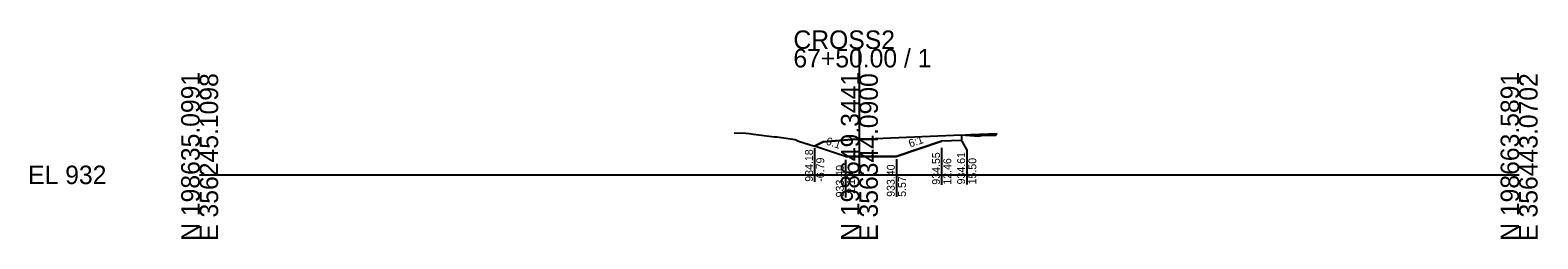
# Model space of a CAD drawing. Extents: x -26 to 203, y -10 to 14021.
# Drawn here: x -25.7 to 202.8, y 8490.3 to 8521.9 of the extents above; entities that cross this region are included whole.
import ezdxf

# ---------------------------------------------------------------- set-up
doc = ezdxf.new("R2010")
doc.units = 0
for name, color, linetype in [('Default', 7, 'Continuous'), ('P_E_XS_Ground', 7, 'Continuous'), ('P_XS', 7, 'Continuous'), ('P_XS_EAR_CommonGrnd', 7, 'Continuous'), ('P_XS_Lane', 7, 'Continuous'), ('P_XS_Rock', 7, 'Continuous')]:
    doc.layers.add(name, color=color, linetype=linetype)

msp = doc.modelspace()

# ---------------------------------------------------------------- linework, layer by layer
at = {"layer": 'Default'}
for p, q in [((100, 8500), (100, 8519.08)), ((0, 8500), (100, 8500)), ((100, 8500), (200, 8500))]:
    msp.add_line(p, q, dxfattribs=at)
at = {"layer": 'P_E_XS_Ground'}
for p, q in [((81.01, 8506.36), (82.8, 8506.3)), ((82.8, 8506.3), (83.28, 8506.29)), ((83.28, 8506.29), (83.94, 8506.16)), ((83.94, 8506.16), (87.15, 8505.77)), ((100, 8505.43), (115.5, 8506.05)), ((115.5, 8506.05), (118.09, 8505.84)), ((118.53, 8505.98), (120.68, 8506)), ((120.68, 8506), (120.89, 8506.23)), ((87.15, 8505.77), (87.53, 8505.74)), ((87.53, 8505.74), (87.86, 8505.71)), ((87.86, 8505.71), (90.25, 8505.35)), ((90.25, 8505.35), (90.77, 8505.13)), ((90.77, 8505.13), (93.21, 8504.37)), ((94.5, 8505.01), (93.21, 8504.37)), ((99.5, 8505.41), (94.5, 8505.01)), ((99.5, 8505.41), (100, 8505.43)), ((118.09, 8505.84), (118.53, 8505.98))]:
    msp.add_line(p, q, dxfattribs=at)
at = {"layer": 'P_XS'}
for p, q in [((116.89, 8506.07), (116.1, 8506)), ((120.89, 8506.23), (116.89, 8506.07))]:
    msp.add_line(p, q, dxfattribs=at)
at = {"layer": 'P_XS_EAR_CommonGrnd'}
msp.add_lwpolyline([(100, 8505.43), (115.5, 8506.05), (116.1, 8506), (115.5, 8505.95), (115.5, 8505.22), (112.46, 8505.1), (105.57, 8502.8), (97.9, 8502.8), (93.21, 8504.37), (94.5, 8505.01), (99.5, 8505.41)], close=True, dxfattribs=at)
at = {"layer": 'P_XS_Lane'}
for p, q in [((116.1, 8506), (115.5, 8505.95)), ((97.9, 8502.8), (93.21, 8504.37)), ((105.57, 8502.8), (112.46, 8505.1)), ((115.5, 8505.22), (112.46, 8505.1)), ((115.5, 8505.95), (115.5, 8505.22)), ((97.9, 8502.8), (105.57, 8502.8))]:
    msp.add_line(p, q, dxfattribs=at)
at = {"layer": 'P_XS_Rock'}
for p, q in [((93.22, 8504.06), (93.22, 8498.95)), ((112.47, 8504.1), (112.47, 8498.51)), ((116.27, 8503.84), (115.57, 8505.1)), ((116.27, 8503.84), (116.27, 8498.55)), ((97.88, 8502.29), (97.88, 8496.59)), ((105.61, 8502.36), (105.61, 8496.66))]:
    msp.add_line(p, q, dxfattribs=at)

# ---------------------------------------------------------------- texts
at = {"layer": 'Default'}
for s, p in [('CROSS2', (90, 8519.08)), ('67+50.00 / 1', (90, 8516.28)), ('EL 932', (-26, 8498.6))]:
    msp.add_text(s, height=2.8, dxfattribs=at).set_placement(p)
for s, p in [('N 198635.0991', (0, 8490)), ('E 356245.1098', (2.8, 8490)), ('N 198649.3441', (100, 8490)), ('E 356344.0900', (102.8, 8490)), ('N 198663.5891', (200, 8490)), ('E 356443.0702', (202.8, 8490))]:
    msp.add_text(s, height=2.8, rotation=90, dxfattribs=at).set_placement(p)
at = {"layer": 'P_XS_Rock'}
for s, rotation, p in [('934.18', 90, (92.97, 8498.96)), ('6:1', 341.5651, (94.83, 8504.64)), ('6:1', 18.4349, (107.69, 8504.14)), ('-6.79', 90, (94.67, 8498.96)), ('933.40', 90, (97.63, 8496.59)), ('933.40', 90, (105.36, 8496.67)), ('934.55', 90, (112.22, 8498.51)), ('12.46', 90, (113.92, 8498.51)), ('934.61', 90, (116.02, 8498.55)), ('15.50', 90, (117.72, 8498.55)), ('-2.10', 90, (99.33, 8496.59)), ('5.57', 90, (107.06, 8496.67))]:
    msp.add_text(s, height=1.2, rotation=rotation, dxfattribs=at).set_placement(p)

doc.saveas('drawing.dxf')
